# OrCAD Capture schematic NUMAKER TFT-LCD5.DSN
size A4; title: NuMaker TFT-LCD5; rev: 1.0; company: nuvoTon Technology Corp.; note: LCD
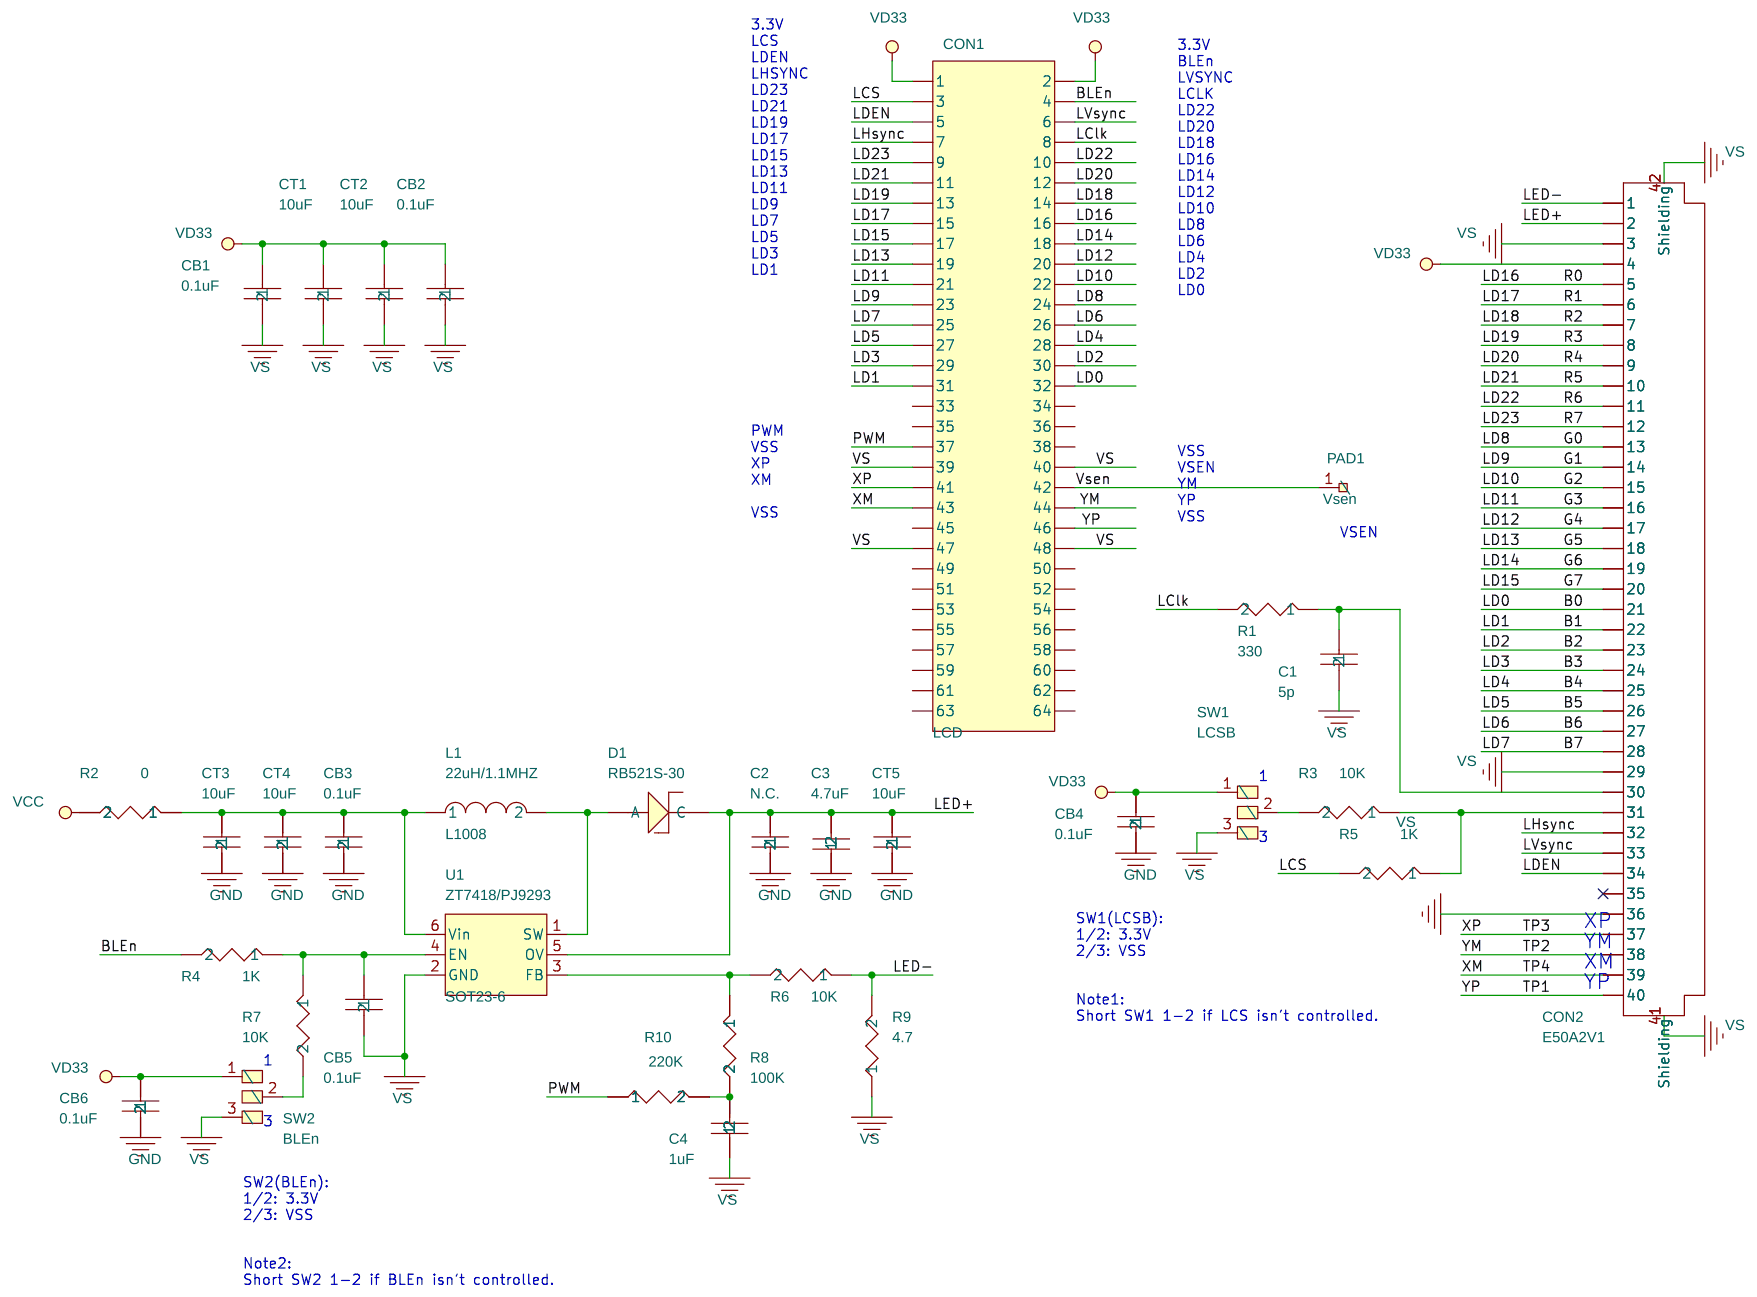
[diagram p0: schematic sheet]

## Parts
C1  5p  [C0603]
C2  N.C.  [C0603]
C3  4.7uF  [C0603]
C4  1uF  [C0603]
CB1  0.1uF  [C0603]
CB2  0.1uF  [C0603]
CB3  0.1uF  [C0603]
CB4  0.1uF  [C0603]
CB5  0.1uF  [C0603]
CB6  0.1uF  [C0603]
CON1  LCD  [F_DIN_32X2/2.54A]
CON2  E50A2V1  [CON0.5mmx40]
CT1  10uF  [C0603]
CT2  10uF  [C0603]
CT3  10uF  [C0603]
CT4  10uF  [C0603]
CT5  10uF  [C0603]
D1  RB521S-30  [Diode_A]
L1  22uH/1.1MHZ  [L1008]
PAD1  Vsen  [1PAD_1.25X1.25MM]
R1  330  [R0603]
R2  0  [R0603]
R3  10K  [R0603]
R4  1K  [R0603]
R5  1K  [R0603]
R6  10K  [R0603]
R7  10K  [R0603]
R8  100K  [R0603]
R9  4.7  [R0603]
R10  220K  [R0603]
SW1  LCSB  [3P-1.2mm]
SW2  BLEn  [3P-1.2mm]
U1  ZT7418/PJ9293  [SOT23-6]

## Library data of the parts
C1 = CAP-B_4: Package: 0603
C2 = CAP-B_5: Package: C0402
C3 = CAP_NP_4
C4 = CAP_NP_2
CB1 = CAP_NP
CB2 = CAP_NP_5
CB3 = CAP-B_3: Package: C0402
CB4 = CAP-B_1: Package: C0402
CB5 = CAP-B: Package: C0402
CB6 = CAP-B_2: Package: C0402
CON1 = CON40A_0
CON2 = LCMCON40x1
CT1 = CAP_NP_6
CT2 = CAP_NP_3
CT3 = CAP_NP_7
CT4 = CAP_NP_1
CT5 = CAP-B_6: Package: C0402
D1 = ZENAR_0: Package: D
L1 = INDUCTOR: Package: L-3
PAD1 = 1PAD_0
R1 = R_2
R2 = R_6: Package: R0402
R3 = R_9: Package: R0402
R4 = R_4: Package: R0402
R5 = R_8: Package: R0402
R6 = R_7: Package: R0402
R7 = R: Package: R0402
R8 = R_3
R9 = R_1: Package: R0402
R10 = R_5
SW1 SW2 = SW-3PAD2
U1 = PJ9293

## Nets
B0: CON1.32 CON2.21
B1: CON1.31 CON2.22
B2: CON1.30 CON2.23
B3: CON1.29 CON2.24
B4: CON1.28 CON2.25
B5: CON1.27 CON2.26
B6: CON1.26 CON2.27
B7: CON1.25 CON2.28
BLEn: CON1.4 R4.2
G0: CON1.24 CON2.13
G1: CON1.23 CON2.14
G2: CON1.22 CON2.15
G3: CON1.21 CON2.16
G4: CON1.20 CON2.17
G5: CON1.19 CON2.18
G6: CON1.18 CON2.19
G7: CON1.17 CON2.20
LClk: CON1.8 R1.2
LCS: CON1.3 R5.2
LD16: CON1.16 CON2.5
LD17: CON1.15 CON2.6
LD18: CON1.14 CON2.7
LD19: CON1.13 CON2.8
LD20: CON1.12 CON2.9
LD21: CON1.11 CON2.10
LD22: CON1.10 CON2.11
LD23: CON1.9 CON2.12
LDEN: CON1.5 CON2.34
LED+: C2.1 C3.2 CON2.2 CT5.1 D1.2(C) U1.5(OV)
LED-: CON2.1 R6.1 R9.2
LHsync: CON1.7 CON2.32
LVsync: CON1.6 CON2.33
PWM: CON1.37 R10.1
TP1: CON1.46 CON2.40
TP2: CON1.44 CON2.38
TP3: CON1.41 CON2.37
TP4: CON1.43 CON2.39
VD33: CB1.1 CB2.1 CB4.1 CB6.1 CON1.1 CON1.2 CON2.4 CT1.1 CT2.1 R2.2 SW1.1(\) SW2.1(\)
VS: C1.2 C2.2 C3.1 C4.1 CB1.2 CB2.2 CB3.2 CB4.2 CB5.2 CB6.2 CON1.39 CON1.40 CON1.47 CON1.48 CON2.3 CON2.29 CON2.36 CON2.41(Shielding) CON2.42(Shielding) CT1.2 CT2.2 CT3.2 CT4.2 CT5.2 R9.1 SW1.3(\) SW2.3(\) U1.2(GND)
Vsen: CON1.42 PAD1.1(\)
N16195231: C1.1 CON2.30 R1.1
N16195511: CON2.31 R3.1 R5.1
N16195927: R3.2 SW1.2(\)
N16198209: CB5.1 R4.1 R7.1 U1.4(EN)
N16198213: CB3.1 CT3.1 CT4.1 L1.1 R2.1 U1.6(Vin)
N16198391: R6.2 R8.1 U1.3(FB)
N16198395: C4.2 R8.2 R10.2
N16198399: R7.2 SW2.2(\)
N16198443: D1.1(A) L1.2 U1.1(SW)

Not connected (* = marked no-connect by the designer): CON1 33 34 35 36 38 45 49 50 51 52 53 54 55 56 57 58 59 60 61 62 63 64; CON2 35*

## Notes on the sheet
- 3.3V
  LCS
  LDEN
  LHSYNC
  LD23
  LD21
  LD19
  LD17
  LD15
  LD13
  LD11
  LD9
  LD7
  LD5
  LD3
  LD1
- 3.3V
  BLEn
  LVSYNC
  LCLK
  LD22
  LD20
  LD18
  LD16
  LD14
  LD12
  LD10
  LD8
  LD6
  LD4
  LD2
  LD0
- PWM
  VSS
  XP
  XM
  VSS
- VSS
  VSEN
  YM
  YP
  VSS
- VSEN
- 1
- 3
- SW1(LCSB):
  1/2: 3.3V
  2/3: VSS
- XP
- YM
- XM
- Note1:
  Short SW1 1-2 if LCS isn't controlled.
- YP
- 1
- 3
- SW2(BLEn):
  1/2: 3.3V
  2/3: VSS
- Note2:
  Short SW2 1-2 if BLEn isn't controlled.
